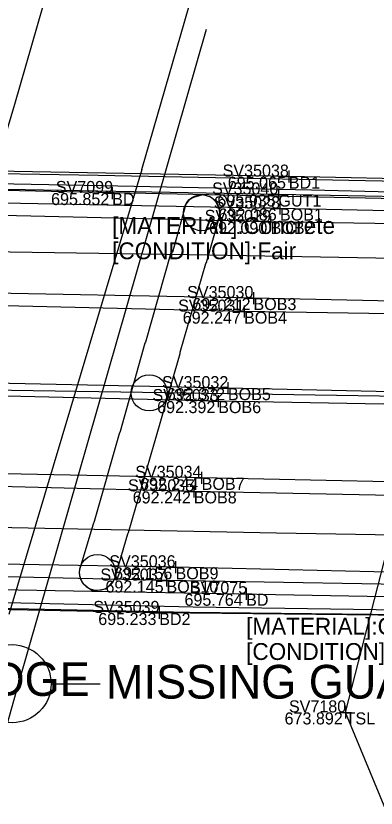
# Model space of a CAD drawing. Extents: x 1659932 to 1663108, y 619867 to 620611.
# Drawn here: x 1661449.7 to 1661479.7, y 620195.1 to 620261 of the extents above; entities that cross this region are included whole.
import ezdxf

# ---------------------------------------------------------------- set-up
doc = ezdxf.new("R2010")
doc.units = 0
for name, color, linetype in [('BR_X_Rail_Object', 7, 'Continuous'), ('BR_X_SV_Bottom_of_Beam', 7, 'Continuous'), ('BR_X_SV_Bottom_of_Beam_Text', 7, 'Continuous'), ('BR_X_SV_Deck_Top', 7, 'Continuous'), ('BR_X_SV_Deck_Top_Text', 7, 'Continuous'), ('BR_X_SV_Pier_Cap_Top', 7, 'Continuous'), ('PM_X_CL_Double_Solid', 7, 'Continuous'), ('PM_X_Edge_Line', 7, 'Continuous'), ('PV_X_Curb', 7, 'Continuous'), ('PV_X_EOP', 7, 'Continuous'), ('RD_X_GR_Rt', 7, 'Continuous'), ('SC_Scratch6', 7, 'Continuous'), ('SV_X_Break_Lines', 7, 'Continuous'), ('SV_X_Shot_Marker', 7, 'Continuous'), ('SV_X_Text', 7, 'Continuous'), ('SV_X_Text_Comment', 7, 'Continuous'), ('SV_X_Text_Elevation', 7, 'Continuous'), ('SV_X_Text_Name', 7, 'Continuous'), ('SV_X_Toe_of_Slope', 7, 'Continuous')]:
    doc.layers.add(name, color=color, linetype=linetype)

msp = doc.modelspace()

# ---------------------------------------------------------------- linework, layer by layer
at = {"layer": 'BR_X_Rail_Object'}
for points in [[(1661525.019, 620245.587), (1661525.344, 620246.45), (1661514.776, 620246.614), (1661499.365, 620246.938), (1661488.433, 620247.052), (1661474.68, 620247.326), (1661456.593, 620247.691), (1661443.635, 620247.905)], [(1661443.687, 620247.108), (1661456.879, 620246.848), (1661474.312, 620246.501), (1661488.734, 620246.14), (1661499.992, 620245.974), (1661515.06, 620245.725), (1661524.66, 620245.538)], [(1661433.513, 620212.015), (1661450.818, 620211.691), (1661464.185, 620211.422), (1661481.921, 620211.226), (1661499.995, 620210.831), (1661515.07, 620210.323)], [(1661515.301, 620210.312), (1661515.369, 620210.843), (1661499.689, 620211.245), (1661481.611, 620211.584), (1661464.483, 620211.85), (1661450.154, 620212.164), (1661434.35, 620212.457)]]:
    msp.add_lwpolyline(points, dxfattribs=at)
at = {"layer": 'BR_X_SV_Bottom_of_Beam'}
for points in [[(1661523.404, 620243.849), (1661497.415, 620244.383), (1661471.694, 620244.95), (1661445.773, 620245.45), (1661419.903, 620245.974), (1661394.009, 620246.51), (1661368.147, 620247.032), (1661342.287, 620247.488), (1661316.311, 620248.045), (1661290.557, 620248.602), (1661264.648, 620249.031), (1661238.6, 620249.579)], [(1661517.582, 620243.008), (1661496.897, 620243.44), (1661470.919, 620243.838), (1661445.09, 620244.441), (1661419.147, 620244.946), (1661393.26, 620245.417), (1661367.358, 620245.921), (1661341.629, 620246.518), (1661315.646, 620247.115), (1661289.746, 620247.518), (1661264.383, 620248.322), (1661238.204, 620248.614)], [(1661521.265, 620236.365), (1661495.332, 620236.959), (1661469.491, 620237.512), (1661443.572, 620237.996), (1661417.708, 620238.508), (1661391.884, 620239.08), (1661365.994, 620239.561), (1661340.119, 620240.034), (1661314.197, 620240.589), (1661288.354, 620241.145), (1661262.476, 620241.611), (1661236.623, 620242.15)], [(1661520.605, 620235.452), (1661494.63, 620235.975), (1661468.71, 620236.383), (1661442.944, 620236.996), (1661417.103, 620237.514), (1661391.103, 620237.982), (1661365.202, 620238.448), (1661339.374, 620239.07), (1661313.502, 620239.591), (1661287.59, 620239.99), (1661261.723, 620240.632), (1661235.908, 620241.144)], [(1661519.081, 620228.953), (1661493.234, 620229.438), (1661467.368, 620230.031), (1661441.422, 620230.57), (1661415.6, 620231.071), (1661389.731, 620231.651), (1661363.823, 620232.132), (1661337.817, 620232.613), (1661311.988, 620233.076), (1661286.183, 620233.721), (1661260.328, 620234.129), (1661234.382, 620234.656)], [(1661518.51, 620227.977), (1661492.527, 620228.475), (1661466.56, 620228.954), (1661440.742, 620229.56), (1661414.823, 620230.069), (1661388.938, 620230.522), (1661363.07, 620231.021), (1661337.298, 620231.612), (1661311.527, 620232.162), (1661285.446, 620232.587), (1661259.588, 620233.138), (1661233.669, 620233.674)], [(1661516.938, 620221.488), (1661491.079, 620222.019), (1661465.187, 620222.58), (1661439.251, 620223.092), (1661413.441, 620223.61), (1661387.584, 620224.174), (1661361.703, 620224.657), (1661335.742, 620225.126), (1661309.876, 620225.693), (1661284.015, 620226.238), (1661258.155, 620226.696), (1661232.1, 620227.235)], [(1661516.255, 620220.542), (1661490.624, 620220.907), (1661464.53, 620221.454), (1661438.64, 620222.101), (1661412.707, 620222.613), (1661386.76, 620223.066), (1661360.949, 620223.557), (1661335.05, 620224.176), (1661309.206, 620224.717), (1661283.267, 620225.126), (1661257.537, 620225.694), (1661231.605, 620226.262)], [(1661514.756, 620214.059), (1661488.914, 620214.555), (1661463.017, 620215.148), (1661437.126, 620215.616), (1661411.256, 620216.167), (1661385.428, 620216.691), (1661359.541, 620217.184), (1661333.602, 620217.682), (1661307.754, 620218.183), (1661281.891, 620218.773), (1661255.858, 620219.275), (1661229.67, 620219.799)], [(1661514.073, 620213.08), (1661488.21, 620213.597), (1661462.263, 620214.044), (1661436.515, 620214.643), (1661410.516, 620215.165), (1661384.602, 620215.601), (1661358.815, 620216.084), (1661332.968, 620216.701), (1661307.113, 620217.251), (1661281.101, 620217.691), (1661255.319, 620218.266), (1661229.464, 620218.851)]]:
    msp.add_lwpolyline(points, dxfattribs=at)
at = {"layer": 'BR_X_SV_Deck_Top'}
for points in [[(1661524.154, 620246.519), (1661498.291, 620247.067), (1661472.426, 620247.598), (1661446.524, 620248.074), (1661420.55, 620248.604), (1661394.772, 620249.021), (1661368.927, 620249.743), (1661342.743, 620250.117), (1661316.866, 620250.706), (1661291.246, 620251.013), (1661265.132, 620251.796)], [(1661513.529, 620210.295), (1661487.664, 620211.099), (1661461.66, 620211.354), (1661435.632, 620211.885), (1661409.962, 620212.424), (1661383.838, 620212.928), (1661332.298, 620213.947), (1661306.248, 620214.439), (1661280.429, 620214.969), (1661254.732, 620215.771)]]:
    msp.add_lwpolyline(points, dxfattribs=at)
at = {"layer": 'BR_X_SV_Pier_Cap_Top'}
msp.add_lwpolyline([(1661457.949, 620214.123), (1661459.066, 620217.938), (1661459.108, 620218.037), (1661461.251, 620225.399), (1661461.259, 620225.493), (1661463.389, 620232.911), (1661463.413, 620233.021), (1661465.531, 620240.392), (1661465.578, 620240.457), (1661466.655, 620244.181), (1661466.695, 620244.41), (1661466.697, 620244.599), (1661466.676, 620244.792), (1661466.628, 620244.99), (1661466.374, 620245.516), (1661466.09, 620245.791), (1661465.867, 620245.915), (1661465.303, 620246.074), (1661464.981, 620246.016), (1661464.52, 620245.877), (1661464.162, 620245.682), (1661463.876, 620245.32), (1661462.772, 620241.319), (1661462.62, 620241.272), (1661460.527, 620233.841), (1661460.469, 620233.763), (1661458.41, 620226.416), (1661458.322, 620226.221), (1661456.245, 620218.948), (1661456.178, 620218.738), (1661455.07, 620215.061), (1661455.013, 620214.775), (1661455.042, 620214.465), (1661455.133, 620214.211), (1661455.31, 620213.801), (1661455.588, 620213.541), (1661456.181, 620213.186), (1661456.53, 620213.242), (1661457.244, 620213.353), (1661457.949, 620214.123)], dxfattribs=at)
at = {"layer": 'PM_X_CL_Double_Solid'}
msp.add_lwpolyline([(1661546.991, 620228.003), (1661534.02, 620228.314), (1661515.703, 620228.672), (1661490.63, 620229.199), (1661465.719, 620229.574), (1661443.889, 620229.917), (1661424.27, 620230.219), (1661405.796, 620230.53), (1661384.669, 620230.881), (1661362.569, 620231.272), (1661341.508, 620231.739), (1661317.992, 620232.235), (1661293.686, 620232.891), (1661270.168, 620233.351), (1661246.396, 620233.829), (1661221.676, 620234.257), (1661205.714, 620234.618)], dxfattribs=at)
at = {"layer": 'PM_X_Edge_Line'}
for points in [[(1661533.637, 620545.425), (1661528.108, 620526.358), (1661523.208, 620509.615), (1661518.012, 620491.429), (1661511.994, 620470.167), (1661507.322, 620453.725), (1661502.995, 620438.636), (1661498.703, 620424.135), (1661495.255, 620412.323), (1661490.204, 620394.571), (1661483.245, 620370.315), (1661475.775, 620344.717), (1661468.35, 620318.812), (1661463.705, 620302.949), (1661458.897, 620285.652), (1661453.934, 620268.511), (1661449.632, 620253.601), (1661448.095, 620248.463)], [(1661550.118, 620239.201), (1661538.667, 620239.519), (1661512.091, 620240.179), (1661488.878, 620240.663), (1661465.84, 620241.071), (1661441.891, 620241.445), (1661414.819, 620241.887), (1661388.375, 620242.338), (1661361.281, 620242.854), (1661333.713, 620243.371), (1661302.167, 620244.004), (1661273.353, 620244.591), (1661246.421, 620245.132), (1661216.402, 620245.664), (1661208.501, 620245.807)], [(1661202.201, 620223.591), (1661213.111, 620223.268), (1661228.394, 620222.766), (1661259.553, 620221.998), (1661275.152, 620221.639), (1661292.516, 620221.273), (1661314.563, 620220.783), (1661337.968, 620220.356), (1661364.828, 620219.904), (1661379.245, 620219.635), (1661405.952, 620219.205), (1661427.476, 620218.875), (1661447.989, 620218.475), (1661471.403, 620218.024), (1661496.022, 620217.585), (1661519.238, 620217.199), (1661540.284, 620216.766), (1661543.975, 620216.723)]]:
    msp.add_lwpolyline(points, dxfattribs=at)
at = {"layer": 'PV_X_Curb'}
msp.add_lwpolyline([(1661523.342, 620245.121), (1661471.566, 620246.113), (1661445.996, 620246.597), (1661316.22, 620249.01), (1661290.79, 620249.439), (1661264.952, 620250.247), (1661238.714, 620250.79)], dxfattribs=at)
at = {"layer": 'PV_X_EOP'}
msp.add_line((1661460.209, 620248.191), (1661449.175, 620211.228), dxfattribs=at)
msp.add_lwpolyline([(1661460.209, 620248.191), (1661465.734, 620267.256), (1661477.474, 620308.258), (1661484.14, 620332.148), (1661489.977, 620352.146), (1661493.172, 620362.868), (1661496.766, 620375.458), (1661502.254, 620394.508), (1661508.039, 620414.587), (1661512.58, 620430.248), (1661515.801, 620441.463), (1661520.55, 620457.989), (1661522.894, 620466.1), (1661527.537, 620482.075), (1661533.623, 620503.392), (1661537.444, 620516.811), (1661543.134, 620536.578)], dxfattribs=at)
at = {"layer": 'RD_X_GR_Rt'}
msp.add_line((1661449.997, 620205.546), (1661465.583, 620259.852), dxfattribs=at)
msp.add_lwpolyline([(1661385.522, 619982.005), (1661394.011, 620012.081), (1661399.542, 620030.546), (1661408.076, 620060.366), (1661416.511, 620089.472), (1661427.104, 620125.794), (1661434.884, 620152.781), (1661444.901, 620187.452), (1661449.997, 620205.546)], dxfattribs=at)
at = {"layer": 'SC_Scratch6'}
msp.add_line((1661452.677, 620205.478), (1661456.767, 620205.478), dxfattribs=at)
msp.add_circle((1661449.432, 620205.478), 3.245, dxfattribs=at)
at = {"layer": 'SV_X_Break_Lines'}
for points in [[(1661238.016, 620250.735), (1661242.286, 620250.672), (1661247.517, 620250.551), (1661257.182, 620250.394), (1661265.859, 620250.202), (1661279.254, 620249.879), (1661300.715, 620249.466), (1661326.88, 620248.933), (1661355.543, 620248.374), (1661388.796, 620247.704), (1661434.33, 620246.78), (1661467.071, 620246.096), (1661484, 620245.717), (1661498.395, 620245.527), (1661509.52, 620245.356), (1661518.819, 620245.069), (1661524.432, 620245.01)], [(1661228.67, 620217.714), (1661237.329, 620217.546), (1661248.531, 620217.329), (1661262.126, 620217.116), (1661283.4, 620216.641), (1661303.8, 620216.137), (1661335.243, 620215.455), (1661384.24, 620214.497), (1661403.674, 620214.086), (1661434.655, 620213.563), (1661466.755, 620212.973), (1661495.661, 620212.446), (1661513.396, 620212.012)]]:
    msp.add_lwpolyline(points, dxfattribs=at)
for centre in [(1661465.187, 620244.602), (1661460.833, 620229.631), (1661456.531, 620214.713)]:
    msp.add_circle(centre, 1.5, dxfattribs=at)
at = {"layer": 'SV_X_Shot_Marker'}
for p, q in [((1661472.426, 620248.098), (1661472.426, 620247.098)), ((1661471.926, 620247.598), (1661472.926, 620247.598)), ((1661472.426, 620247.598), (1661472.426, 620247.598)), ((1661457.25, 620246.236), (1661458.25, 620246.236)), ((1661457.75, 620246.736), (1661457.75, 620245.736)), ((1661457.75, 620246.236), (1661457.75, 620246.236)), ((1661471.066, 620246.113), (1661472.066, 620246.113)), ((1661471.566, 620246.613), (1661471.566, 620245.613)), ((1661471.566, 620246.113), (1661471.566, 620246.113)), ((1661471.694, 620245.45), (1661471.694, 620244.45)), ((1661471.194, 620244.95), (1661472.194, 620244.95)), ((1661471.694, 620244.95), (1661471.694, 620244.95)), ((1661470.919, 620244.338), (1661470.919, 620243.338)), ((1661470.419, 620243.838), (1661471.419, 620243.838)), ((1661470.919, 620243.838), (1661470.919, 620243.838)), ((1661469.491, 620238.012), (1661469.491, 620237.012)), ((1661468.71, 620236.883), (1661468.71, 620235.883)), ((1661468.991, 620237.512), (1661469.991, 620237.512)), ((1661469.491, 620237.512), (1661469.491, 620237.512)), ((1661468.21, 620236.383), (1661469.21, 620236.383)), ((1661468.71, 620236.383), (1661468.71, 620236.383)), ((1661467.368, 620230.531), (1661467.368, 620229.531)), ((1661466.868, 620230.031), (1661467.868, 620230.031)), ((1661467.368, 620230.031), (1661467.368, 620230.031)), ((1661466.56, 620229.454), (1661466.56, 620228.454)), ((1661466.06, 620228.954), (1661467.06, 620228.954)), ((1661466.56, 620228.954), (1661466.56, 620228.954)), ((1661465.187, 620223.08), (1661465.187, 620222.08)), ((1661464.687, 620222.58), (1661465.687, 620222.58)), ((1661465.187, 620222.58), (1661465.187, 620222.58)), ((1661464.53, 620221.954), (1661464.53, 620220.954)), ((1661464.03, 620221.454), (1661465.03, 620221.454)), ((1661464.53, 620221.454), (1661464.53, 620221.454)), ((1661463.017, 620215.648), (1661463.017, 620214.648)), ((1661462.263, 620214.544), (1661462.263, 620213.544)), ((1661462.517, 620215.148), (1661463.517, 620215.148)), ((1661463.017, 620215.148), (1661463.017, 620215.148)), ((1661461.763, 620214.044), (1661462.763, 620214.044)), ((1661462.263, 620214.044), (1661462.263, 620214.044)), ((1661468.881, 620213.452), (1661468.881, 620212.452)), ((1661468.381, 620212.952), (1661469.381, 620212.952)), ((1661468.881, 620212.952), (1661468.881, 620212.952)), ((1661461.16, 620211.354), (1661462.16, 620211.354)), ((1661461.66, 620211.854), (1661461.66, 620210.854)), ((1661461.66, 620211.354), (1661461.66, 620211.354)), ((1661477.149, 620203.596), (1661477.149, 620202.596)), ((1661476.649, 620203.096), (1661477.649, 620203.096)), ((1661477.149, 620203.096), (1661477.149, 620203.096))]:
    msp.add_line(p, q, dxfattribs=at)
at = {"layer": 'SV_X_Toe_of_Slope'}
msp.add_lwpolyline([(1661490.605, 620170.614), (1661477.149, 620203.096), (1661498.786, 620287.484), (1661510.242, 620298.378), (1661539.687, 620302.32)], dxfattribs=at)

# ---------------------------------------------------------------- texts
at = {"layer": 'BR_X_SV_Bottom_of_Beam_Text'}
for s, p in [('SV35028', (1661466.197, 620244.95)), ('SV35029', (1661465.439, 620243.838)), ('692.086', (1661466.59, 620243.95)), ('BOB1', (1661471.694, 620243.95)), ('692.090', (1661465.805, 620242.838)), ('BOB2', (1661470.919, 620242.838)), ('SV35030', (1661463.981, 620237.512)), ('692.212', (1661464.418, 620236.512)), ('BOB3', (1661469.491, 620236.512)), ('SV35031', (1661463.232, 620236.383)), ('692.247', (1661463.614, 620235.383)), ('BOB4', (1661468.71, 620235.383)), ('SV35032', (1661461.899, 620230.031)), ('SV35033', (1661461.1, 620228.954)), ('692.372', (1661462.295, 620229.031)), ('BOB5', (1661467.368, 620229.031)), ('692.392', (1661461.487, 620227.954)), ('BOB6', (1661466.56, 620227.954)), ('SV35034', (1661459.669, 620222.58)), ('SV35035', (1661459.063, 620221.454)), ('692.244', (1661460.065, 620221.58)), ('BOB7', (1661465.187, 620221.58)), ('692.242', (1661459.457, 620220.454)), ('BOB8', (1661464.53, 620220.454)), ('SV35036', (1661457.517, 620215.148)), ('692.156', (1661457.913, 620214.148)), ('BOB9', (1661463.017, 620214.148)), ('SV35037', (1661456.771, 620214.044)), ('692.145', (1661457.193, 620213.044)), ('BOB10', (1661462.263, 620213.044))]:
    msp.add_text(s, height=1, dxfattribs=at).set_placement(p)
at = {"layer": 'BR_X_SV_Deck_Top_Text'}
for s, p in [('SV35038', (1661466.929, 620247.598)), ('695.065', (1661467.356, 620246.598)), ('BD1', (1661472.426, 620246.598)), ('SV7099', (1661453.068, 620246.236)), ('695.852', (1661452.677, 620245.236)), ('BD', (1661457.75, 620245.236)), ('SV7075', (1661464.212, 620212.952)), ('695.764', (1661463.759, 620211.952)), ('BD', (1661468.881, 620211.952)), ('SV35039', (1661456.18, 620211.354)), ('695.233', (1661456.596, 620210.354)), ('BD2', (1661461.66, 620210.354))]:
    msp.add_text(s, height=1, dxfattribs=at).set_placement(p)
at = {"layer": 'SC_Scratch6'}
for s, p in [('MISSING FENCE UNDER THE BRIDGE', (1661388.066, 620204.466)), ('MISSING GUADRAIL BEYOND THIS', (1661457.236, 620204.242))]:
    msp.add_text(s, height=2.79999, dxfattribs=at).set_placement(p)
at = {"layer": 'SV_X_Text'}
for s, p in [('[MATERIAL]:Concrete', (1661457.75, 620242.836)), ('[CONDITION]:Fair', (1661457.75, 620240.736)), ('[MATERIAL]:Concrete', (1661468.881, 620209.552)), ('[CONDITION]:Fair', (1661468.881, 620207.452))]:
    msp.add_text(s, height=1.4, dxfattribs=at).set_placement(p)
at = {"layer": 'SV_X_Text_Comment'}
for s, p in [('GUT1', (1661471.566, 620245.113)), ('TSL', (1661477.149, 620202.096))]:
    msp.add_text(s, height=1, dxfattribs=at).set_placement(p)
at = {"layer": 'SV_X_Text_Elevation'}
for s, p in [('695.935', (1661466.496, 620245.113)), ('673.892', (1661472.076, 620202.096))]:
    msp.add_text(s, height=1, dxfattribs=at).set_placement(p)
at = {"layer": 'SV_X_Text_Name'}
for s, p in [('SV35040', (1661466.056, 620246.113)), ('SV7180', (1661472.437, 620203.096))]:
    msp.add_text(s, height=1, dxfattribs=at).set_placement(p)

doc.saveas('drawing.dxf')
